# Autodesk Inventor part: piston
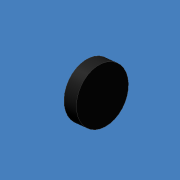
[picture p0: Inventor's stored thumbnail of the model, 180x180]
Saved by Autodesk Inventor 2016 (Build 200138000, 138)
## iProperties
Shininess: 20.0
Angle Display Precision: 2
Document Length Units: 11269
Document Angle Units: 11279
Document Time Units: 11290
Document Mass Units: 11283
Document Length Units Precision: 3
Document Angle Units Precision: 2
Compacted: True
Created: 2002-09
Part Number: piston
Material: Acier
Document SubType Name: Modélisation
Designer: administrateur
Mass: 98.646 g
Surface Area: 37.6991 cm^2
Volume: 12.5664 cm^3
Density: 7.85 g/cm^3
Appearance: Noir
Density: 0.0
Volumn: 0.0
Area: 0.0
PropertySet Name: Model Information
Control State: 0
Master: False
Checked Out: False
Author: administrateur
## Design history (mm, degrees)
sketch "Esquisse1"
  geometry: C1 r 20 at (0, 0)
  constraints: 1 centre point
  dimensions: "d0" = 40 dimension on C1.centre C1; "d0" = 40 diameter of C1
extrude "Extrusion1" new body sketch "Esquisse1" distance "d1" = 10; taper "d2" = 0 deg
node "Solide1"
node "Corps solides"
node "Corps surfaciques"
